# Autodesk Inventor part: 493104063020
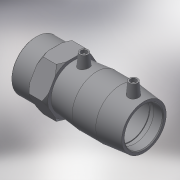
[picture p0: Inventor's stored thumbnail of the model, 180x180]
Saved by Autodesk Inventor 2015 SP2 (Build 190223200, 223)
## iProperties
Created: 2017-06
Part Number: 493104063020
Material: Generic
Description: PLASSON FEMALE TRANSITION COUPLER 63-2"
Document SubType Name: Modeling
Designer: KIM
Mass: 387.644 g
Surface Area: 734.235 cm^2
Volume: 387.644 cm^3
Density: 1 g/cm^3
Appearance: Default
Author: KIM
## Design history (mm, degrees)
derived "493104.ipt"
feature "Solid1::493104.ipt"
tag "TaggingFeature1"
body "Solid1"
other parameters: "d0" = 117, "d1" = 63, "d2" = 82, "d3" = 57, "d4" = 39, "d5" = 73.8, "d6" = 59.85, "d7" = 63, "d8" = 168 deg, "d10" = 22.8, "d11" = 7.6, "d29" = 57, "d30" = 14, "d31" = 40.95, "d34" = 5 deg, "d41" = 4, "d42" = 14, "d43" = 0, "d48" = 3, "d49" = 0, "d57" = 48, "d59" = 56.656, "d60" = 27, "d70" = 82, "d71" = 15, "d72" = 0, "d73" = 45 deg, "d74" = 4.8, "d75" = 45 deg, "d77" = 0.945, "d80" = 1.26, "d_" = 63, "L_" = 147, "L_1" = 57, "D_1" = 82, "A_" = 57, "d_2" = 12, "D_" = 48, "R_p" = 56.656
